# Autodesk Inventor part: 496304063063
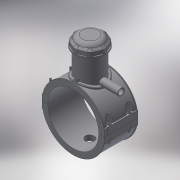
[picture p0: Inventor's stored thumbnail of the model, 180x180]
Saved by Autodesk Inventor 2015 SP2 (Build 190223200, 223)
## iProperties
Created: 2017-07
Part Number: 496304063063
Material: Generic
Description: PLASSON TAPPING SADDLE 63x63
Document SubType Name: Modeling
Designer: KIM
Mass: 646.499 g
Surface Area: 1727.31 cm^2
Volume: 646.499 cm^3
Density: 1 g/cm^3
Appearance: Default
Author: KIM
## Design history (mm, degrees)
derived "496304.ipt"
feature "Solid1::496304.ipt"
feature "Solid2::496304.ipt"
feature "Solid4::496304.ipt"
feature "Solid5::496304.ipt"
tag "TaggingFeature1"
body "Solid1"
body "Solid2"
other parameters: "d0" = 63, "d3" = 15.75, "d4" = 118, "d5" = 0, "d6" = 0.1, "d8" = 0, "d19" = 6, "d20" = 6, "d21" = 70.8, "d23" = 0, "d24" = 35.4, "d26" = 0, "d29" = 3, "d30" = 21, "d31" = 6, "d32" = 0, "d33" = 0, "d34" = 0.6, "d40" = 42.588, "d41" = 75.6, "d43" = 0, "d45" = 0, "d47" = 111.75, "d70" = 15, "d72" = 0, "d73" = 6, "d75" = 5, "d76" = 0, "d77" = 3.15, "d78" = 61.5, "d79" = 15, "d80" = 47.2, "d82" = 5 deg, "d84" = 4, "d85" = 14, "d86" = 0, "d87" = 3, "d88" = 0, "d89" = 1, "d90" = 1, "d91" = 94.4, "d92" = 0, "d93" = 0.5, "d94" = 33.15789, "d96" = 83.538, "d97" = 2.36, "d98" = 0, "d102" = 0.63, "d120" = 140 deg, "d121" = 24.228, "d122" = 20 deg, "d123" = 163.8, "d124" = 49.14, "d126" = 0, "d143" = 64.89, "d145" = 14.53846, "d149" = 0.945, "d150" = 15.99231, "d153" = 118, "d154" = 0, "d156" = 40.95, "d157" = 160 deg, "d159" = 3.78, "d161" = 0.945, "d162" = 70.8, "d163" = 0, "d164" = 31.5, "d167" = 6.3, "d168" = 39.95122, "d170" = 3.375, "d172" = 0, "d173" = 1, "d175" = 31.5, "d176" = 20 deg, "d177" = 4.41, "d178" = 18.9, "d180" = 0, "d183" = 7.56, "d184" = 3.528, "d185" = 38.35, "d186" = 38.35, "d187" = 40.95, "d188" = 5.67, "d189" = 4.41, "d190" = 0, "d191" = 61.425, "d193" = 6.3, "d194" = 4.13, "d195" = 90 deg, "d197" = 0, "d199" = 0, "d200" = 9.45, "d202" = 0, "d203" = 177, "d204" = 71.82, "d205" = 52.92, "d206" = 64.26, "d207" = 132.75, "d208" = 138.06, "d209" = 164.61, "d210" = 65.016, "d211" = 75.6, "d212" = 60.48, "d213" = 29.25, "d216" = 0, "d217" = 6.3, "d218" = 6.3, "d219" = 1.26, "d222" = 63, "d224" = 0, "d230" = 3.78, "d233" = 6, "d237" = 35.4, "d238" = 6.02433, "d240" = 35.4, "d241" = 35.4, "d242" = 35.4, "d243" = 6, "d244" = 35.4, "d245" = 35.4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
